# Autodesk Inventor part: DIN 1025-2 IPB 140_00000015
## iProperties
Created: 2006-02
Part Number: DIN 1025-2 IPB 140_00000015
Material: Default
Document SubType Name: Modeling
Designer: 40664
Manufacturer: Standard
Standards Organization: Custom
Stock Number: DIN 1025-2 IPB 140
Mass: 11082.7 g
Surface Area: 20865.2 cm^2
Volume: 11082.7 cm^3
Density: 1 g/cm^3
G_L: 2580.000 mm
G_W: 140.000 mm
G_H: 140.000 mm
AFG_Item: IPB 140
CSToolsMass: 11.0
CSToolsVolume: 11082691.0
CSToolsArea: 20865.0
Author: 40664
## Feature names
1. AFG_Detailed_DIN 1025-2 IPB 140_00000015 [Extrusion]
2. AFG_Simplified_DIN 1025-2 IPB 140_00000015 [Extrusion]
